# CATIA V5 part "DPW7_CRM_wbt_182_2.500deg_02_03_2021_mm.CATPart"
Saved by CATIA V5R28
Part number: DPW7_CRM_wbt_182_2.500deg_02_03_2021
Bounding box of the stored display mesh (mm): x 2349.5 to 66711.891, y 0 to 29448.592, z 2310.119 to 8715.756
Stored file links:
  Z:\Scratch\04_CAD_Allgemein\Flight2Jig\Output\DPW-7\CATPart\DPW7_CRM_wbt_182_2.500deg_02_03_2021.CATPart
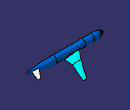
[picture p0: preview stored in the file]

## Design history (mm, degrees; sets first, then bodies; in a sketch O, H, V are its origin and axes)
Set1
  DatumSurface1 "Clean_Wing"
  DatumSurface2 "Fuselage"
  DatumSurface3 "HTP"
  DatumSurface4 "Symmetry"
  DatumSurface5 "Farfield"
Body1 (main body)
